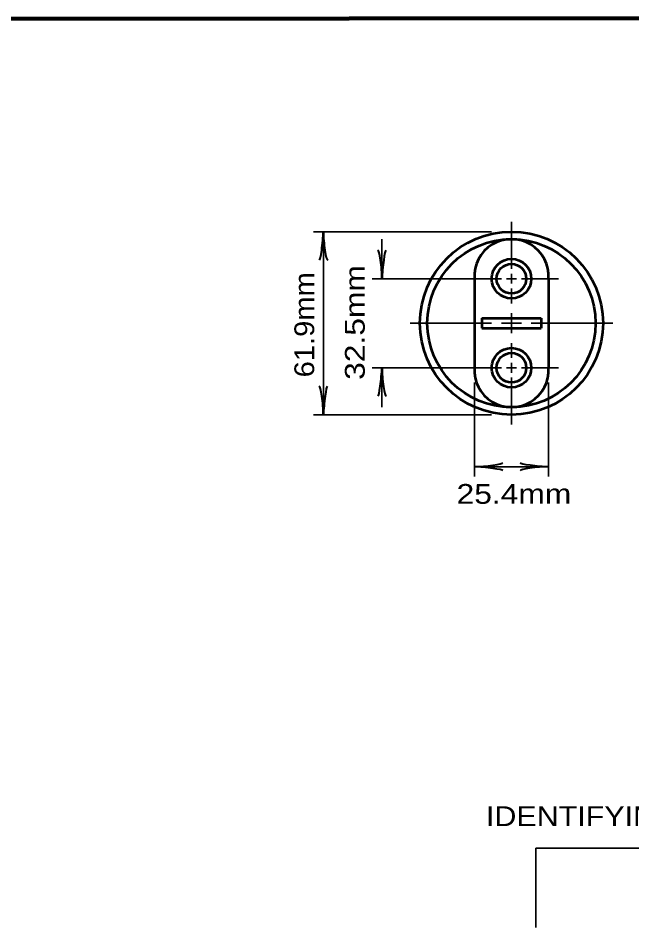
# Model space of a CAD drawing. Extents: x -32 to 824, y -6 to 538.
# Drawn here: x 513.4 to 587.8, y 421.3 to 531.7 of the extents above; entities that cross this region are included whole.
import ezdxf

# ---------------------------------------------------------------- set-up
doc = ezdxf.new("R2010")
doc.units = 0
doc.header["$LTSCALE"] = 1.1
doc.layers.add('1', color=7, linetype='Continuous', lineweight=53)

msp = doc.modelspace()

# ---------------------------------------------------------------- linework, layer by layer
at = {"layer": '1', "lineweight": 35}
for p, q in [((573.187, 507.051), (573.187, 501.351)), ((570.787, 505.851), (549.187, 505.851)), ((550.387, 505.851), (550.387, 483.651)), ((557.489, 504.951), (557.489, 500.151)), ((573.187, 500.751), (573.187, 499.551)), ((556.289, 500.151), (571.987, 500.151)), ((572.587, 500.151), (573.787, 500.151)), ((574.387, 500.151), (578.887, 500.151)), ((573.187, 498.951), (573.187, 497.151)), ((560.887, 494.751), (570.787, 494.751)), ((575.587, 494.751), (585.487, 494.751)), ((573.187, 492.351), (573.187, 490.551)), ((556.289, 489.351), (571.987, 489.351)), ((557.489, 489.351), (557.489, 484.551)), ((572.587, 489.351), (573.787, 489.351)), ((573.187, 489.951), (573.187, 488.751)), ((574.387, 489.351), (578.887, 489.351)), ((573.187, 488.151), (573.187, 482.451)), ((568.687, 487.551), (568.687, 476.151)), ((577.687, 487.551), (577.687, 476.151)), ((570.787, 483.651), (549.187, 483.651)), ((568.687, 477.351), (577.687, 477.351)), ((621.736, 431.073), (576.136, 431.073)), ((576.136, 431.073), (576.136, 421.473))]:
    msp.add_line(p, q, dxfattribs=at)
at = {"layer": '1'}
for p, q in [((568.687, 500.151), (568.687, 494.751)), ((577.687, 500.151), (577.687, 494.751)), ((569.587, 495.351), (573.187, 495.351)), ((569.587, 495.351), (569.587, 494.151)), ((573.187, 495.351), (576.787, 495.351)), ((576.787, 495.351), (576.787, 494.151)), ((568.687, 494.751), (568.687, 489.351)), ((569.587, 494.151), (573.187, 494.151)), ((573.187, 494.151), (576.787, 494.151)), ((577.687, 494.751), (577.687, 489.351))]:
    msp.add_line(p, q, dxfattribs=at)
at = {"layer": '1', "lineweight": 158}
msp.add_lwpolyline([(817.398, 531.744), (25.698, 531.644), (25.798, 5.644)], dxfattribs=at)
at = {"layer": '1', "lineweight": 35}
for points in [[(573.187, 495.951), (573.187, 494.751), (573.187, 493.551)], [(571.987, 494.751), (573.187, 494.751), (574.387, 494.751)]]:
    msp.add_lwpolyline(points, dxfattribs=at)
at = {"layer": '1'}
for centre, radius in [((573.187, 494.751), 11.1), ((573.187, 494.751), 10.2), ((573.187, 500.151), 2.4), ((573.187, 500.151), 1.8), ((573.187, 489.351), 2.4), ((573.187, 489.351), 1.8)]:
    msp.add_circle(centre, radius, dxfattribs=at)
for centre, start, end in [((573.187, 500.441), 356.30478, 183.69522), ((573.187, 489.06), 176.30478, 3.69522)]:
    msp.add_arc(centre, 4.509, start, end, dxfattribs=at)
at = {"layer": '1', "lineweight": 40}
for centre, major_axis, ratio, start_param, end_param in [((550.133, 504.506), (0.211, 2.108), 0.07063, 3.1407148, 5.41811), ((550.133, 504.506), (0.211, 2.108), 0.07063, 3.1407148, 5.41811), ((550.719, 504.541), (-0.187, 2.143), 0.122415, 0.8963533, 3.1415927), ((550.719, 504.541), (-0.187, 2.143), 0.122415, 0.8963533, 3.1415927), ((557.158, 501.46), (0.187, -2.143), 0.122415, 0.8963533, 3.1415927), ((557.743, 501.495), (-0.211, -2.108), 0.07063, 3.1407148, 5.41811), ((557.235, 488.006), (0.211, 2.108), 0.07063, 3.1407148, 5.41811), ((557.821, 488.041), (-0.187, 2.143), 0.122415, 0.8963533, 3.1415927), ((550.056, 484.96), (0.187, -2.143), 0.122415, 0.8963533, 3.1415927), ((550.641, 484.995), (-0.211, -2.108), 0.07063, 3.1407148, 5.41811), ((570.032, 477.097), (-2.108, 0.211), 0.07063, 3.1407148, 5.41811), ((570.032, 477.097), (-2.108, 0.211), 0.07063, 3.1407148, 5.41811), ((569.997, 477.682), (-2.143, -0.187), 0.122415, 0.8963533, 3.1415927), ((569.997, 477.682), (-2.143, -0.187), 0.122415, 0.8963533, 3.1415927), ((576.378, 477.019), (2.143, 0.187), 0.122415, 0.8963533, 3.1415927), ((576.343, 477.605), (2.108, -0.211), 0.07063, 3.1407148, 5.41811)]:
    msp.add_ellipse(centre, major_axis=major_axis, ratio=ratio, start_param=start_param, end_param=end_param, dxfattribs=at)

# ---------------------------------------------------------------- texts
at = {"layer": '1'}
for s, width, p in [('32.5mm', 1.2, (555.402, 487.881)), ('61.9mm', 1.1, (549.269, 488.184))]:
    msp.add_text(s, height=2.4, rotation=90, dxfattribs=dict(at, width=width)).set_placement(p)
for s, width, p in [('25.4mm', 1.2, (566.533, 472.848)), ('IDENTIFYING SYMBOLS III -', 1.15, (570.096, 433.76))]:
    msp.add_text(s, height=2.4, dxfattribs=dict(at, width=width)).set_placement(p)

doc.saveas('drawing.dxf')
